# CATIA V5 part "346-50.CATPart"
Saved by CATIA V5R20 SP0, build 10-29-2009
Part number: 346-50
Definition: NONE
Nomenclature: 346-50
Source: Unknown
Description: 346-50
Bounding box of the stored display mesh (mm): x 0 to 100, y -51.5 to 51.5, z -51.5 to 51.5
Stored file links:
  C:\Users\Utente\Desktop\IO LAVORO\3D X SITO CF\X SITO\3D files 346\346-50.CATPart
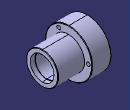
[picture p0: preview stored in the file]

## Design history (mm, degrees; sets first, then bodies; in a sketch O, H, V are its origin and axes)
Body1 "346-50" (main body)
  Solid1: solid without history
